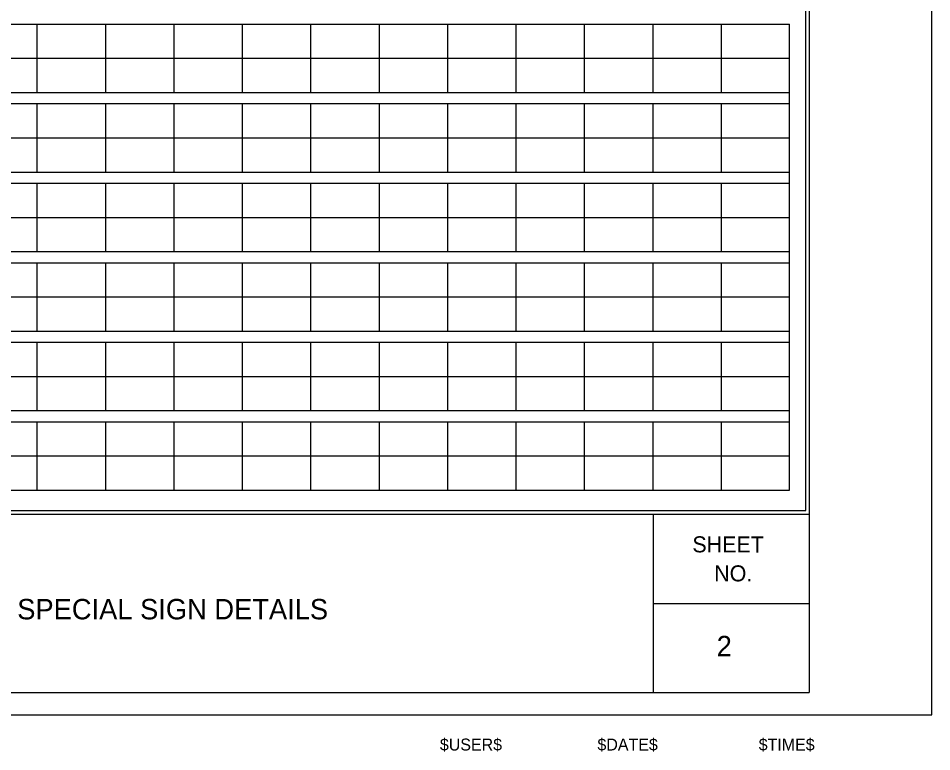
# Model space of a CAD drawing. Extents: x 17890628 to 17890844, y 17897506 to 17897992.
# Drawn here: x 17890808.43 to 17890844.15, y 17897506.37 to 17897535.03 of the extents above; entities that cross this region are included whole.
import ezdxf

# ---------------------------------------------------------------- set-up
doc = ezdxf.new("R2010")
doc.units = 0
for name, color, linetype in [('PlotBorder_dp', 7, 'Continuous'), ('SheetBorder_dp', 7, 'Continuous'), ('SheetLines_dp', 7, 'Continuous'), ('SheetLinesMisc2_dp', 7, 'Continuous'), ('TextMisc', 7, 'Continuous')]:
    doc.layers.add(name, color=color, linetype=linetype)

msp = doc.modelspace()

# ---------------------------------------------------------------- linework, layer by layer
at = {"layer": 'PlotBorder_dp'}
msp.add_lwpolyline([(17890700.471, 17897507.81), (17890844.155, 17897507.81), (17890844.155, 17897600.116), (17890700.471, 17897600.116)], close=True, dxfattribs=at)
at = {"layer": 'SheetBorder_dp'}
for p, q in [((17890839.365, 17897599.245), (17890839.365, 17897508.681)), ((17890705.26, 17897515.647), (17890839.365, 17897515.647)), ((17890705.26, 17897508.681), (17890839.365, 17897508.681))]:
    msp.add_line(p, q, dxfattribs=at)
at = {"layer": 'SheetLines_dp'}
for p, q in [((17890833.27, 17897508.681), (17890833.27, 17897515.647)), ((17890833.27, 17897512.164), (17890839.365, 17897512.164))]:
    msp.add_line(p, q, dxfattribs=at)
at = {"layer": 'SheetLinesMisc2_dp'}
for p, q in [((17890839.233, 17897515.791), (17890839.233, 17897599.038)), ((17890772.824, 17897534.804), (17890838.594, 17897534.804)), ((17890809.164, 17897534.804), (17890809.164, 17897532.131)), ((17890811.839, 17897534.804), (17890811.839, 17897532.131)), ((17890814.514, 17897534.804), (17890814.514, 17897532.131)), ((17890817.19, 17897534.804), (17890817.19, 17897532.131)), ((17890819.866, 17897534.804), (17890819.866, 17897532.131)), ((17890822.541, 17897534.804), (17890822.541, 17897532.131)), ((17890825.216, 17897534.804), (17890825.216, 17897532.131)), ((17890827.892, 17897534.804), (17890827.892, 17897532.131)), ((17890830.568, 17897534.804), (17890830.568, 17897532.131)), ((17890833.243, 17897534.804), (17890833.243, 17897532.131)), ((17890835.919, 17897534.804), (17890835.919, 17897532.131)), ((17890838.594, 17897516.593), (17890838.594, 17897534.804)), ((17890772.824, 17897533.468), (17890838.594, 17897533.468)), ((17890772.824, 17897532.131), (17890838.594, 17897532.131)), ((17890772.824, 17897531.696), (17890838.594, 17897531.696)), ((17890809.164, 17897531.696), (17890809.164, 17897529.023)), ((17890811.839, 17897531.696), (17890811.839, 17897529.023)), ((17890814.514, 17897531.696), (17890814.514, 17897529.023)), ((17890817.19, 17897531.696), (17890817.19, 17897529.023)), ((17890819.866, 17897531.696), (17890819.866, 17897529.023)), ((17890822.541, 17897531.696), (17890822.541, 17897529.023)), ((17890825.216, 17897531.696), (17890825.216, 17897529.023)), ((17890827.892, 17897531.696), (17890827.892, 17897529.023)), ((17890830.568, 17897531.696), (17890830.568, 17897529.023)), ((17890833.243, 17897531.696), (17890833.243, 17897529.023)), ((17890835.919, 17897531.696), (17890835.919, 17897529.023)), ((17890772.824, 17897530.359), (17890838.594, 17897530.359)), ((17890772.824, 17897529.023), (17890838.594, 17897529.023)), ((17890772.824, 17897528.588), (17890838.594, 17897528.588)), ((17890809.164, 17897528.588), (17890809.164, 17897525.916)), ((17890811.839, 17897528.588), (17890811.839, 17897525.916)), ((17890814.514, 17897528.588), (17890814.514, 17897525.916)), ((17890817.19, 17897528.588), (17890817.19, 17897525.916)), ((17890819.866, 17897528.588), (17890819.866, 17897525.916)), ((17890822.541, 17897528.588), (17890822.541, 17897525.916)), ((17890825.216, 17897528.588), (17890825.216, 17897525.916)), ((17890827.892, 17897528.588), (17890827.892, 17897525.916)), ((17890830.568, 17897528.588), (17890830.568, 17897525.916)), ((17890833.243, 17897528.588), (17890833.243, 17897525.916)), ((17890835.919, 17897528.588), (17890835.919, 17897525.916)), ((17890772.824, 17897527.252), (17890838.594, 17897527.252)), ((17890772.824, 17897525.916), (17890838.594, 17897525.916)), ((17890772.824, 17897525.48), (17890838.594, 17897525.48)), ((17890809.164, 17897525.48), (17890809.164, 17897522.808)), ((17890811.839, 17897525.48), (17890811.839, 17897522.808)), ((17890814.514, 17897525.48), (17890814.514, 17897522.808)), ((17890817.19, 17897525.48), (17890817.19, 17897522.808)), ((17890819.866, 17897525.48), (17890819.866, 17897522.808)), ((17890822.541, 17897525.48), (17890822.541, 17897522.808)), ((17890825.216, 17897525.48), (17890825.216, 17897522.808)), ((17890827.892, 17897525.48), (17890827.892, 17897522.808)), ((17890830.568, 17897525.48), (17890830.568, 17897522.808)), ((17890833.243, 17897525.48), (17890833.243, 17897522.808)), ((17890835.919, 17897525.48), (17890835.919, 17897522.808)), ((17890772.824, 17897524.145), (17890838.594, 17897524.145)), ((17890772.824, 17897522.808), (17890838.594, 17897522.808)), ((17890772.824, 17897522.372), (17890838.594, 17897522.372)), ((17890809.164, 17897522.372), (17890809.164, 17897519.7)), ((17890811.839, 17897522.372), (17890811.839, 17897519.7)), ((17890814.514, 17897522.372), (17890814.514, 17897519.7)), ((17890817.19, 17897522.372), (17890817.19, 17897519.7)), ((17890819.866, 17897522.372), (17890819.866, 17897519.7)), ((17890822.541, 17897522.372), (17890822.541, 17897519.7)), ((17890825.216, 17897522.372), (17890825.216, 17897519.7)), ((17890827.892, 17897522.372), (17890827.892, 17897519.7)), ((17890830.568, 17897522.372), (17890830.568, 17897519.7)), ((17890833.243, 17897522.372), (17890833.243, 17897519.7)), ((17890835.919, 17897522.372), (17890835.919, 17897519.7)), ((17890772.824, 17897521.036), (17890838.594, 17897521.036)), ((17890772.824, 17897519.7), (17890838.594, 17897519.7)), ((17890772.824, 17897519.264), (17890838.594, 17897519.264)), ((17890809.164, 17897519.264), (17890809.164, 17897516.593)), ((17890811.839, 17897519.264), (17890811.839, 17897516.593)), ((17890814.514, 17897519.264), (17890814.514, 17897516.593)), ((17890817.19, 17897519.264), (17890817.19, 17897516.593)), ((17890819.866, 17897519.264), (17890819.866, 17897516.593)), ((17890822.541, 17897519.264), (17890822.541, 17897516.593)), ((17890825.216, 17897519.264), (17890825.216, 17897516.593)), ((17890827.892, 17897519.264), (17890827.892, 17897516.593)), ((17890830.568, 17897519.264), (17890830.568, 17897516.593)), ((17890833.243, 17897519.264), (17890833.243, 17897516.593)), ((17890835.919, 17897519.264), (17890835.919, 17897516.593)), ((17890772.824, 17897517.928), (17890838.594, 17897517.928)), ((17890772.824, 17897516.593), (17890838.594, 17897516.593)), ((17890705.5, 17897515.791), (17890839.233, 17897515.791))]:
    msp.add_line(p, q, dxfattribs=at)

# ---------------------------------------------------------------- texts
at = {"layer": 'TextMisc'}
for s, p in [('SHEET', (17890834.794, 17897514.158)), ('NO.', (17890835.647, 17897513.026))]:
    msp.add_text(s, height=0.627, rotation=359.8607, dxfattribs=at).set_placement(p)
for s, height, p in [('SPECIAL SIGN DETAILS', 0.79796, (17890808.392, 17897511.539)), ('2', 0.798, (17890835.745, 17897510.096)), ('$USER$', 0.467, (17890824.921, 17897506.413)), ('$DATE$', 0.467, (17890831.082, 17897506.413)), ('$TIME$', 0.467, (17890837.389, 17897506.413))]:
    msp.add_text(s, height=height, dxfattribs=at).set_placement(p)

doc.saveas('drawing.dxf')
